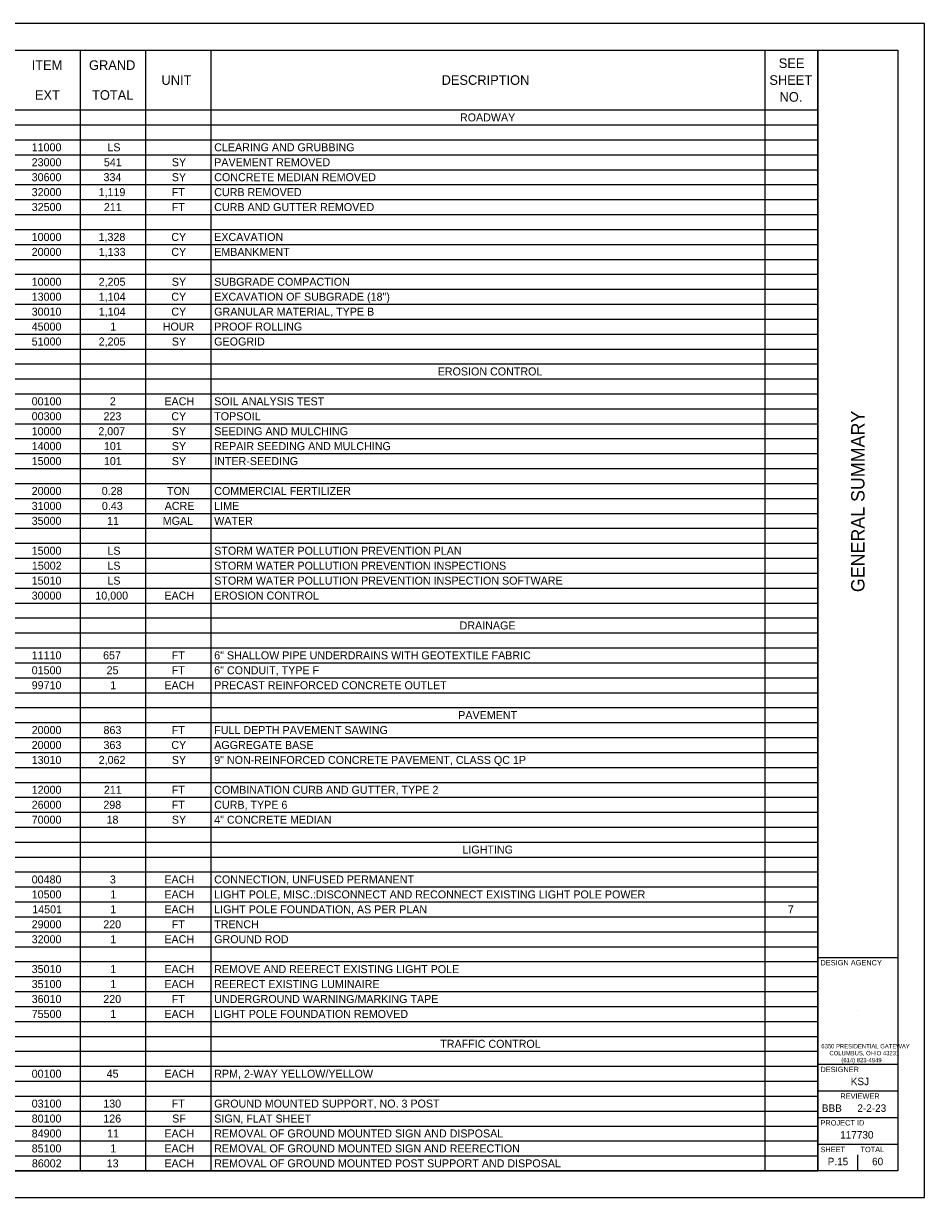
# Model space of a CAD drawing. Extents: x 0 to 34, y 0 to 22.
# Drawn here: x 17.11 to 34, y 0 to 22 of the extents above; entities that cross this region are included whole.
import ezdxf

# ---------------------------------------------------------------- set-up
doc = ezdxf.new("R2010")
doc.units = 0
for name, color, linetype in [('SH_Border', 7, 'Continuous'), ('SH_Cut_Line', 7, 'Continuous'), ('SH_Data', 7, 'Continuous'), ('SH_Text', 7, 'Continuous')]:
    doc.layers.add(name, color=color, linetype=linetype)

msp = doc.modelspace()

# ---------------------------------------------------------------- linework, layer by layer
at = {"layer": 'SH_Border'}
for p, q in [((32, 0.5), (32, 21.5)), ((32, 4.5), (33.5, 4.5)), ((32, 2.5), (33.5, 2.5)), ((32, 2), (33.5, 2)), ((32, 1.5), (33.5, 1.5)), ((32, 1), (33.5, 1))]:
    msp.add_line(p, q, dxfattribs=at)
msp.add_lwpolyline([(1.5, 21.5), (33.5, 21.5), (33.5, 0.5), (1.5, 0.5)], close=True, dxfattribs=at)
at = {"layer": 'SH_Cut_Line'}
msp.add_lwpolyline([(0, 0), (34, 0), (34, 22), (0, 22)], close=True, dxfattribs=at)
at = {"layer": 'SH_Data'}
for p, q in [((32.75, 3.5), (32.75, 3.5)), ((32.375, 0.675), (32.375, 0.675)), ((32.75, 0.5), (32.75, 0.8))]:
    msp.add_line(p, q, dxfattribs=at)
at = {"layer": 'SH_Text'}
for p, q in [((1.5, 21.5), (32, 21.5)), ((18.176, 21.5), (18.176, 0.5)), ((19.399, 21.5), (19.399, 0.5)), ((20.621, 21.5), (20.621, 0.5)), ((31.005, 21.5), (31.005, 0.5)), ((32, 21.5), (32, 0.5)), ((1.5, 20.38), (32, 20.38)), ((1.5, 20.1), (32, 20.1)), ((1.5, 19.82), (32, 19.82)), ((1.5, 19.54), (32, 19.54)), ((1.5, 19.26), (32, 19.26)), ((1.5, 18.98), (32, 18.98)), ((1.5, 18.7), (32, 18.7)), ((1.5, 18.42), (32, 18.42)), ((1.5, 18.14), (32, 18.14)), ((1.5, 17.86), (32, 17.86)), ((1.5, 17.58), (32, 17.58)), ((1.5, 17.3), (32, 17.3)), ((1.5, 17.02), (32, 17.02)), ((1.5, 16.74), (32, 16.74)), ((1.5, 16.46), (32, 16.46)), ((1.5, 16.18), (32, 16.18)), ((1.5, 15.9), (32, 15.9)), ((1.5, 15.62), (32, 15.62)), ((1.5, 15.34), (32, 15.34)), ((1.5, 15.06), (32, 15.06)), ((1.5, 14.78), (32, 14.78)), ((1.5, 14.5), (32, 14.5)), ((1.5, 14.22), (32, 14.22)), ((1.5, 13.94), (32, 13.94)), ((1.5, 13.66), (32, 13.66)), ((1.5, 13.38), (32, 13.38)), ((1.5, 13.1), (32, 13.1)), ((1.5, 12.82), (32, 12.82)), ((1.5, 12.54), (32, 12.54)), ((1.5, 12.26), (32, 12.26)), ((1.5, 11.98), (32, 11.98)), ((1.5, 11.7), (32, 11.7)), ((1.5, 11.42), (32, 11.42)), ((1.5, 11.14), (32, 11.14)), ((1.5, 10.86), (32, 10.86)), ((1.5, 10.58), (32, 10.58)), ((1.5, 10.3), (32, 10.3)), ((1.5, 10.02), (32, 10.02)), ((1.5, 9.74), (32, 9.74)), ((1.5, 9.46), (32, 9.46)), ((1.5, 9.18), (32, 9.18)), ((1.5, 8.9), (32, 8.9)), ((1.5, 8.62), (32, 8.62)), ((1.5, 8.34), (32, 8.34)), ((1.5, 8.06), (32, 8.06)), ((1.5, 7.78), (32, 7.78)), ((1.5, 7.5), (32, 7.5)), ((1.5, 7.22), (32, 7.22)), ((1.5, 6.94), (32, 6.94)), ((1.5, 6.66), (32, 6.66)), ((1.5, 6.38), (32, 6.38)), ((1.5, 6.1), (32, 6.1)), ((1.5, 5.82), (32, 5.82)), ((1.5, 5.54), (32, 5.54)), ((1.5, 5.26), (32, 5.26)), ((1.5, 4.98), (32, 4.98)), ((1.5, 4.7), (32, 4.7)), ((1.5, 4.42), (32, 4.42)), ((1.5, 4.14), (32, 4.14)), ((1.5, 3.86), (32, 3.86)), ((1.5, 3.58), (32, 3.58)), ((1.5, 3.3), (32, 3.3)), ((1.5, 3.02), (32, 3.02)), ((1.5, 2.74), (32, 2.74)), ((1.5, 2.46), (32, 2.46)), ((1.5, 2.18), (32, 2.18)), ((1.5, 1.9), (32, 1.9)), ((1.5, 1.62), (32, 1.62)), ((1.5, 1.34), (32, 1.34)), ((1.5, 1.06), (32, 1.06)), ((1.5, 0.78), (32, 0.78)), ((1.5, 0.5), (32, 0.5))]:
    msp.add_line(p, q, dxfattribs=at)

# ---------------------------------------------------------------- texts
at = {"layer": 'SH_Data'}
msp.add_text('GENERAL SUMMARY', height=0.25, rotation=90, dxfattribs=at).set_placement((32.875, 11.344))
for s, height, p in [('DESIGN AGENCY', 0.1, (32.05, 4.35)), ('6350 PRESIDENTIAL GATEWAY', 0.08, (32.065, 2.795)), ('COLUMBUS, OHIO 43231', 0.08, (32.218, 2.665)), ('DESIGNER', 0.1, (32.05, 2.35)), ('(614) 823-4949', 0.08, (32.441, 2.535)), ('KSJ', 0.14, (32.617, 2.105)), ('REVIEWER', 0.1, (32.422, 1.85)), ('BBB', 0.14, (32.075, 1.605)), ('2-2-23', 0.14, (32.741, 1.605)), ('PROJECT ID', 0.1, (32.05, 1.35)), ('117730', 0.14, (32.419, 1.105)), ('SHEET', 0.1, (32.05, 0.85)), ('TOTAL', 0.1, (32.8, 0.85)), ('P.15', 0.14, (32.185, 0.605)), ('60', 0.14, (33.017, 0.605))]:
    msp.add_text(s, height=height, dxfattribs=at).set_placement(p)
at = {"layer": 'SH_Text'}
for s, height, p in [('SEE ', 0.18, (31.268, 21.166)), ('ITEM', 0.18, (17.266, 21.13)), ('GRAND', 0.18, (18.34, 21.13)), ('UNIT', 0.18, (19.698, 20.85)), ('DESCRIPTION', 0.18, (24.949, 20.85)), ('SHEET ', 0.18, (31.092, 20.85)), ('EXT', 0.18, (17.326, 20.57)), ('TOTAL', 0.18, (18.397, 20.57)), ('NO.', 0.18, (31.283, 20.534)), ('ROADWAY', 0.15, (25.293, 20.165)), ('11000', 0.15, (17.266, 19.605)), ('LS', 0.15, (18.685, 19.605)), ('CLEARING AND GRUBBING', 0.15, (20.687, 19.605)), ('23000', 0.15, (17.266, 19.325)), ('541', 0.15, (18.619, 19.325)), ('SY', 0.15, (19.893, 19.325)), ('PAVEMENT REMOVED', 0.15, (20.687, 19.325)), ('30600', 0.15, (17.266, 19.045)), ('334', 0.15, (18.612, 19.045)), ('SY', 0.15, (19.893, 19.045)), ('CONCRETE MEDIAN REMOVED', 0.15, (20.687, 19.045)), ('32000', 0.15, (17.266, 18.765)), ('1,119', 0.15, (18.52, 18.765)), ('FT', 0.15, (19.89, 18.765)), ('CURB REMOVED', 0.15, (20.687, 18.765)), ('32500', 0.15, (17.266, 18.485)), ('211', 0.15, (18.619, 18.485)), ('FT', 0.15, (19.89, 18.485)), ('CURB AND GUTTER REMOVED', 0.15, (20.687, 18.485)), ('10000', 0.15, (17.266, 17.925)), ('1,328', 0.15, (18.519, 17.925)), ('CY', 0.15, (19.883, 17.925)), ('EXCAVATION', 0.15, (20.687, 17.925)), ('20000', 0.15, (17.266, 17.645)), ('1,133', 0.15, (18.523, 17.645)), ('CY', 0.15, (19.883, 17.645)), ('EMBANKMENT', 0.15, (20.687, 17.645)), ('10000', 0.15, (17.266, 17.085)), ('2,205', 0.15, (18.521, 17.085)), ('SY', 0.15, (19.893, 17.085)), ('SUBGRADE COMPACTION', 0.15, (20.687, 17.085)), ('13000', 0.15, (17.266, 16.805)), ('1,104', 0.15, (18.523, 16.805)), ('CY', 0.15, (19.883, 16.805)), ('EXCAVATION OF SUBGRADE (18")', 0.15, (20.687, 16.805)), ('30010', 0.15, (17.266, 16.525)), ('1,104', 0.15, (18.523, 16.525)), ('CY', 0.15, (19.883, 16.525)), ('GRANULAR MATERIAL, TYPE B', 0.15, (20.687, 16.525)), ('45000', 0.15, (17.266, 16.245)), ('1', 0.15, (18.738, 16.245)), ('HOUR', 0.15, (19.722, 16.245)), ('PROOF ROLLING', 0.15, (20.687, 16.245)), ('51000', 0.15, (17.266, 15.965)), ('2,205', 0.15, (18.521, 15.965)), ('SY', 0.15, (19.893, 15.965)), ('GEOGRID', 0.15, (20.687, 15.965)), ('EROSION CONTROL', 0.15, (24.876, 15.405)), ('00100', 0.15, (17.266, 14.845)), ('2', 0.15, (18.731, 14.845)), ('EACH', 0.15, (19.753, 14.845)), ('SOIL ANALYSIS TEST', 0.15, (20.687, 14.845)), ('00300', 0.15, (17.266, 14.565)), ('223', 0.15, (18.612, 14.565)), ('CY', 0.15, (19.883, 14.565)), ('TOPSOIL', 0.15, (20.687, 14.565)), ('10000', 0.15, (17.266, 14.285)), ('2,007', 0.15, (18.515, 14.285)), ('SY', 0.15, (19.893, 14.285)), ('SEEDING AND MULCHING', 0.15, (20.687, 14.285)), ('14000', 0.15, (17.266, 14.005)), ('101', 0.15, (18.619, 14.005)), ('SY', 0.15, (19.893, 14.005)), ('REPAIR SEEDING AND MULCHING', 0.15, (20.687, 14.005)), ('15000', 0.15, (17.266, 13.725)), ('101', 0.15, (18.619, 13.725)), ('SY', 0.15, (19.893, 13.725)), ('INTER-SEEDING', 0.15, (20.687, 13.725)), ('20000', 0.15, (17.266, 13.165)), ('0.28', 0.15, (18.579, 13.165)), ('TON', 0.15, (19.803, 13.165)), ('COMMERCIAL FERTILIZER', 0.15, (20.687, 13.165)), ('31000', 0.15, (17.266, 12.885)), ('0.43', 0.15, (18.582, 12.885)), ('ACRE', 0.15, (19.759, 12.885)), ('LIME', 0.15, (20.687, 12.885)), ('35000', 0.15, (17.266, 12.605)), ('11', 0.15, (18.679, 12.605)), ('MGAL', 0.15, (19.722, 12.605)), ('WATER', 0.15, (20.687, 12.605)), ('15000', 0.15, (17.266, 12.045)), ('LS', 0.15, (18.685, 12.045)), ('STORM WATER POLLUTION PREVENTION PLAN', 0.15, (20.687, 12.045)), ('15002', 0.15, (17.269, 11.765)), ('LS', 0.15, (18.685, 11.765)), ('STORM WATER POLLUTION PREVENTION INSPECTIONS', 0.15, (20.687, 11.765)), ('15010', 0.15, (17.266, 11.485)), ('LS', 0.15, (18.685, 11.485)), ('STORM WATER POLLUTION PREVENTION INSPECTION SOFTWARE', 0.15, (20.687, 11.485)), ('30000', 0.15, (17.266, 11.205)), ('10,000', 0.15, (18.459, 11.205)), ('EACH', 0.15, (19.753, 11.205)), ('EROSION CONTROL', 0.15, (20.687, 11.205)), ('DRAINAGE', 0.15, (25.286, 10.645)), ('11110', 0.15, (17.266, 10.085)), ('657', 0.15, (18.604, 10.085)), ('FT', 0.15, (19.89, 10.085)), ('6" SHALLOW PIPE UNDERDRAINS WITH GEOTEXTILE FABRIC', 0.15, (20.687, 10.085)), ('01500', 0.15, (17.266, 9.805)), ('25', 0.15, (18.67, 9.805)), ('FT', 0.15, (19.89, 9.805)), ('6" CONDUIT, TYPE F', 0.15, (20.687, 9.805)), ('99710', 0.15, (17.266, 9.525)), ('1', 0.15, (18.738, 9.525)), ('EACH', 0.15, (19.753, 9.525)), ('PRECAST REINFORCED CONCRETE OUTLET', 0.15, (20.687, 9.525)), ('PAVEMENT', 0.15, (25.261, 8.965)), ('20000', 0.15, (17.266, 8.685)), ('863', 0.15, (18.612, 8.685)), ('FT', 0.15, (19.89, 8.685)), ('FULL DEPTH PAVEMENT SAWING', 0.15, (20.687, 8.685)), ('20000', 0.15, (17.266, 8.405)), ('363', 0.15, (18.612, 8.405)), ('CY', 0.15, (19.883, 8.405)), ('AGGREGATE BASE', 0.15, (20.687, 8.405)), ('13010', 0.15, (17.266, 8.125)), ('2,062', 0.15, (18.522, 8.125)), ('SY', 0.15, (19.893, 8.125)), ('9" NON-REINFORCED CONCRETE PAVEMENT, CLASS QC 1P', 0.15, (20.687, 8.125)), ('12000', 0.15, (17.266, 7.565)), ('211', 0.15, (18.619, 7.565)), ('FT', 0.15, (19.89, 7.565)), ('COMBINATION CURB AND GUTTER, TYPE 2', 0.15, (20.687, 7.565)), ('26000', 0.15, (17.266, 7.285)), ('298', 0.15, (18.609, 7.285)), ('FT', 0.15, (19.89, 7.285)), ('CURB, TYPE 6', 0.15, (20.687, 7.285)), ('70000', 0.15, (17.266, 7.005)), ('18', 0.15, (18.669, 7.005)), ('SY', 0.15, (19.893, 7.005)), ('4" CONCRETE MEDIAN', 0.15, (20.687, 7.005)), ('LIGHTING', 0.15, (25.339, 6.445)), ('00480', 0.15, (17.266, 5.885)), ('3', 0.15, (18.732, 5.885)), ('EACH', 0.15, (19.753, 5.885)), ('CONNECTION, UNFUSED PERMANENT', 0.15, (20.687, 5.885)), ('10500', 0.15, (17.266, 5.605)), ('1', 0.15, (18.738, 5.605)), ('EACH', 0.15, (19.753, 5.605)), ('LIGHT POLE, MISC.:DISCONNECT AND RECONNECT EXISTING LIGHT POLE POWER', 0.15, (20.687, 5.605)), ('14501', 0.15, (17.276, 5.325)), ('1', 0.15, (18.738, 5.325)), ('EACH', 0.15, (19.753, 5.325)), ('LIGHT POLE FOUNDATION, AS PER PLAN', 0.15, (20.687, 5.325)), ('7', 0.15, (31.439, 5.325)), ('29000', 0.15, (17.266, 5.045)), ('220', 0.15, (18.608, 5.045)), ('FT', 0.15, (19.89, 5.045)), ('TRENCH', 0.15, (20.687, 5.045)), ('32000', 0.15, (17.266, 4.765)), ('1', 0.15, (18.738, 4.765)), ('EACH', 0.15, (19.753, 4.765)), ('GROUND ROD', 0.15, (20.687, 4.765)), ('35010', 0.15, (17.266, 4.205)), ('1', 0.15, (18.738, 4.205)), ('EACH', 0.15, (19.753, 4.205)), ('REMOVE AND REERECT EXISTING LIGHT POLE', 0.15, (20.687, 4.205)), ('35100', 0.15, (17.266, 3.925)), ('1', 0.15, (18.738, 3.925)), ('EACH', 0.15, (19.753, 3.925)), ('REERECT EXISTING LUMINAIRE', 0.15, (20.687, 3.925)), ('36010', 0.15, (17.266, 3.645)), ('220', 0.15, (18.608, 3.645)), ('FT', 0.15, (19.89, 3.645)), ('UNDERGROUND WARNING/MARKING TAPE', 0.15, (20.687, 3.645)), ('75500', 0.15, (17.266, 3.365)), ('1', 0.15, (18.738, 3.365)), ('EACH', 0.15, (19.753, 3.365)), ('LIGHT POLE FOUNDATION REMOVED', 0.15, (20.687, 3.365)), ('TRAFFIC CONTROL', 0.15, (24.923, 2.805)), ('00100', 0.15, (17.266, 2.245)), ('45', 0.15, (18.67, 2.245)), ('EACH', 0.15, (19.753, 2.245)), ('RPM, 2-WAY YELLOW/YELLOW', 0.15, (20.687, 2.245)), ('03100', 0.15, (17.266, 1.685)), ('130', 0.15, (18.608, 1.685)), ('FT', 0.15, (19.89, 1.685)), ('GROUND MOUNTED SUPPORT, NO. 3 POST', 0.15, (20.687, 1.685)), ('80100', 0.15, (17.266, 1.405)), ('126', 0.15, (18.608, 1.405)), ('SF', 0.15, (19.899, 1.405)), ('SIGN, FLAT SHEET', 0.15, (20.687, 1.405)), ('84900', 0.15, (17.266, 1.125)), ('11', 0.15, (18.679, 1.125)), ('EACH', 0.15, (19.753, 1.125)), ('REMOVAL OF GROUND MOUNTED SIGN AND DISPOSAL', 0.15, (20.687, 1.125)), ('85100', 0.15, (17.266, 0.845)), ('1', 0.15, (18.738, 0.845)), ('EACH', 0.15, (19.753, 0.845)), ('REMOVAL OF GROUND MOUNTED SIGN AND REERECTION', 0.15, (20.687, 0.845)), ('86002', 0.15, (17.269, 0.565)), ('13', 0.15, (18.672, 0.565)), ('EACH', 0.15, (19.753, 0.565)), ('REMOVAL OF GROUND MOUNTED POST SUPPORT AND DISPOSAL', 0.15, (20.687, 0.565))]:
    msp.add_text(s, height=height, dxfattribs=at).set_placement(p)

doc.saveas('drawing.dxf')
